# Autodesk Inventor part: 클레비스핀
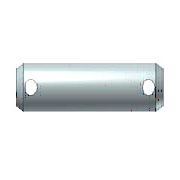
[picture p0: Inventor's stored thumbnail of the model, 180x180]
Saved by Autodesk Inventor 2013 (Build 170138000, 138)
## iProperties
IsCustomPart: 1
Created: 2012-02
Part Number: 클레비스핀
Material: 강철
Description: 머리가 없는 클레비스 핀 B
Document SubType Name: Modeling
Standard: ISO 2340
Designer: mduedu
Standard Revision: Second edition 1986-11-01
Standards Organization: ISO
Language: ko-KR
Size Designation: B - 8 x 45
Categories: <MemberInstance><Categories><Category DisplayName="조임쇠" InternalName="e4da775c-781d-43d5-af7c-5136215cf5a6" Mnemonic="FSTN"><Category DisplayName="핀" InternalNa
Density: 7.85 g/cm^3
Author: mduedu
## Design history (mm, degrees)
sketch "스케치1"
  geometry: L1 (-4.5, 0)-(-4.5, 4); L2 (-4.5, 4)-(35.5, 4); L3 (35.5, 4)-(35.5, 0); L4 (-4.5, 0)-(35.5, 0); L5 (0, -2)-(0, 5) reference; L6 (-13.5, 0)-(49.5, 0) reference; C1 r 1 at (-1, 0); C2 r 1 at (32, 0)
  constraints: 8 end point, 2 centre point, 2 perpendicular, 2 point on line, 1 collinear, 1 parallel, 1 tangent, 1 vertical
  dimensions: "d0" = 8 diameter of L2 L4 (= NND); "d1" = 40 distance of L1.end L2.end (= NLG); "d2" = 3.5 distance from line of L1 C1.centre (= DIST1); "d3" = 3.5 distance from line of L3 C2.centre (= DIST2); "d4" = 2 diameter of C1 (= BOR1); "d5" = 2 diameter of C2 (= BOR2)
revolve "본체" stored, may be unused: angle "d7" = 90 deg
extrude "구멍1" cut sketch "스케치1" taper "d6" = 0 deg; stored distance "d8" = 10
extrude "구멍2" cut sketch "스케치1" taper "d13" = 0 deg; stored distance "d14" = 10
workaxis "Work Axis1"
workaxis "Work Axis2"
workplane "Work Plane1"
node "작업 평면5"
body "Solid1"
chamfer "모따기2" distance "d9" = 2 (= PHH2); stored, may be unused: angle "d10" = 30 deg (= FAWI2), second distance "d40" = 2 (= PHH2)
chamfer "모따기1" distance "d11" = 2 (= PHH1); stored, may be unused: angle "d12" = 30 deg (= FAWI1), second distance "d41" = 2 (= PHH1)
other parameters: "NLG" = 40 [user parameter; used in 1 equation term], "NND" = 8 [user parameter; used in 1 equation term], "PHH1" = 2 [user parameter; used in 3 equation terms], "PHH2" = 2 (= PHH1) [user parameter; used in 2 equation terms], "FAWI1" = 30 deg [user parameter; used in 1 equation term], "FAWI2" = 30 deg [user parameter; used in 1 equation term], "DIST1" = 3.5 [user parameter; used in 4 equation terms], "DIST2" = 3.5 (= DIST1) [user parameter; used in 1 equation term], "BOR1" = 2 [user parameter; used in 4 equation terms], "BOR2" = 2 (= BOR1) [user parameter; used in 1 equation term], "d15" = 0, "d42" = 0, "d43" = 0, "d44" = -4.5 (= -0.5 x BOR1 - DIST1), "d45" = -4.5 (= -0.5 x BOR1 - DIST1), "d47" = 0, "d48" = 0, "d49" = 0, "d50" = 0, "d51" = 0, "d52" = 0
